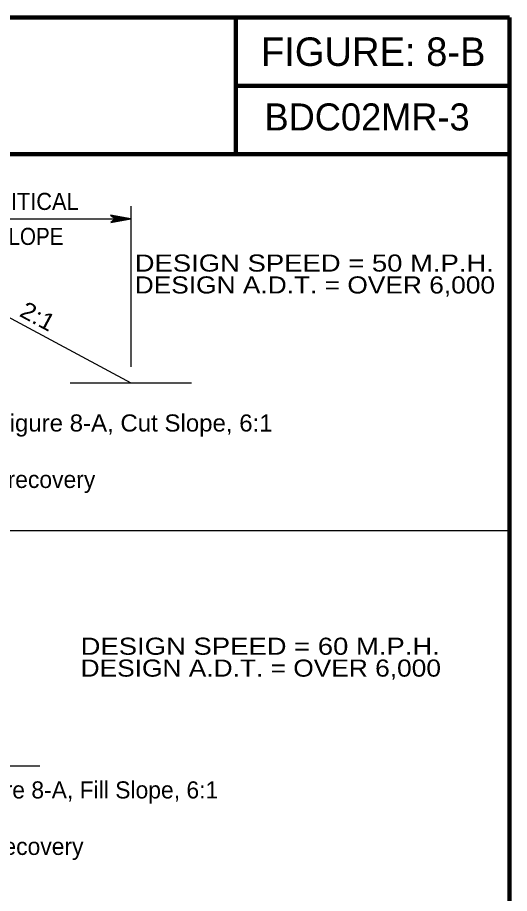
# Model space of a CAD drawing. Extents: x -15.691 to -15.016, y -14.8 to -13.916.
# Drawn here: x -15.2866 to -15.0618, y -14.3626 to -13.9621 of the extents above; entities that cross this region are included whole.
import ezdxf
from ezdxf.enums import TextEntityAlignment as Align

# ---------------------------------------------------------------- set-up
doc = ezdxf.new("R2010")
doc.units = 0
doc.header["$LTSCALE"] = 0.0031
for name, color, linetype, lineweight in [('1', 7, 'Continuous', 90), ('24', 7, 'Continuous', 25), ('5', 7, 'Continuous', 25)]:
    doc.layers.add(name, color=color, linetype=linetype, lineweight=lineweight)

msp = doc.modelspace()

# ---------------------------------------------------------------- linework, layer by layer
at = {"layer": '1'}
for p, q in [((-15.186808, -13.962108), (-15.186808, -14.024608)), ((-15.061808, -13.962108), (-15.061808, -14.753775)), ((-15.061808, -13.962108), (-15.061808, -14.753775)), ((-15.186808, -13.993358), (-15.061808, -13.993358)), ((-15.645142, -14.024608), (-15.061808, -14.024608))]:
    msp.add_line(p, q, dxfattribs=at)
msp.add_lwpolyline([(-15.645142, -13.962108), (-15.186808, -13.962108), (-15.061808, -13.962108)], dxfattribs=at)
at = {"layer": '24'}
for p, q in [((-15.234825, -14.048383), (-15.234825, -14.12175)), ((-15.327883, -14.054167), (-15.234825, -14.054167))]:
    msp.add_line(p, q, dxfattribs=at)
msp.add_lwpolyline([(-15.234825, -14.054167), (-15.244067, -14.052533), (-15.241858, -14.054167), (-15.244017, -14.055775), (-15.234825, -14.054167), (-15.235442, -14.054183), (-15.243808, -14.05265), (-15.241683, -14.054183), (-15.243642, -14.05565), (-15.235775, -14.054208), (-15.236075, -14.054167), (-15.24325, -14.052892), (-15.241642, -14.054183), (-15.243292, -14.055442), (-15.236217, -14.054167), (-15.236525, -14.054208), (-15.242792, -14.053083), (-15.241575, -14.054167), (-15.242817, -14.055292), (-15.237417, -14.054217), (-15.237942, -14.054208), (-15.242325, -14.053317), (-15.241475, -14.054142), (-15.242392, -14.055058), (-15.238033, -14.054167), (-15.238525, -14.054142), (-15.241825, -14.053575), (-15.241192, -14.054217), (-15.241875, -14.054842), (-15.238983, -14.054167), (-15.239442, -14.054117), (-15.241425, -14.053742), (-15.2411, -14.054183), (-15.241642, -14.054683), (-15.239683, -14.054167), (-15.240975, -14.053858), (-15.240792, -14.054208), (-15.241358, -14.054567), (-15.240008, -14.054217), (-15.240858, -14.054), (-15.240508, -14.054283), (-15.240908, -14.05445), (-15.240508, -14.054183), (-15.240717, -14.054142)], dxfattribs=at)
at = {"layer": '5'}
for p, q in [((-15.327883, -14.079167), (-15.234825, -14.129167)), ((-15.2626, -14.129167), (-15.234825, -14.129167)), ((-15.234825, -14.129167), (-15.20705, -14.129167)), ((-15.645142, -14.196558), (-15.061808, -14.196558)), ((-15.304267, -14.304167), (-15.276492, -14.304167))]:
    msp.add_line(p, q, dxfattribs=at)

# ---------------------------------------------------------------- texts
at = {"layer": '1'}
for s, height, p in [('FIGURE: 8-B', 0.01303, (-15.124075, -13.98425)), ('BDC02MR-3', 0.01237, (-15.126879, -14.013742))]:
    msp.add_text(s, height=height, dxfattribs=at).set_placement(p, align=Align.CENTER)
for s, width, p in [('CRITICAL', 0.95, (-15.28135, -14.050075)), ('SLOPE', 0.9, (-15.28135, -14.066075))]:
    msp.add_text(s, height=0.007817, dxfattribs=dict(at, width=width)).set_placement(p, align=Align.CENTER)
for s, width, p in [('DESIGN SPEED = 50 M.P.H.', 1.2, (-15.233083, -14.078267)), ('DESIGN A.D.T. = OVER 6,000', 1.15, (-15.233083, -14.088267)), ('The suggested clear zone distance for the 2% slope (See Figure 8-A, Cut Slope, 6:1', 1.05, (-15.578825, -14.151367)), ('DESIGN SPEED = 60 M.P.H.', 1.2, (-15.2578, -14.253433)), ('DESIGN A.D.T. = OVER 6,000', 1.15, (-15.2578, -14.263433))]:
    msp.add_text(s, height=0.007817, dxfattribs=dict(at, width=width)).set_placement(p)
at = {"layer": '1', "width": 1.1}
msp.add_text('2:1', height=0.007817, rotation=331.75, dxfattribs=at).set_placement((-15.279212, -14.102153), align=Align.CENTER)
at = {"layer": '1'}
for s, p in [('The available 23 feet is 1 to 3 feet greater than the suggested recovery', (-15.578825, -14.177183)), ('The suggested clear zone distance for the 8% slope (See Figure 8-A, Fill Slope, 6:1', (-15.581308, -14.319125)), ('The available 17 feet is 13 to 15 feet less than the suggested recovery', (-15.581308, -14.344942))]:
    msp.add_text(s, height=0.007817, dxfattribs=at).set_placement(p)

doc.saveas('drawing.dxf')
